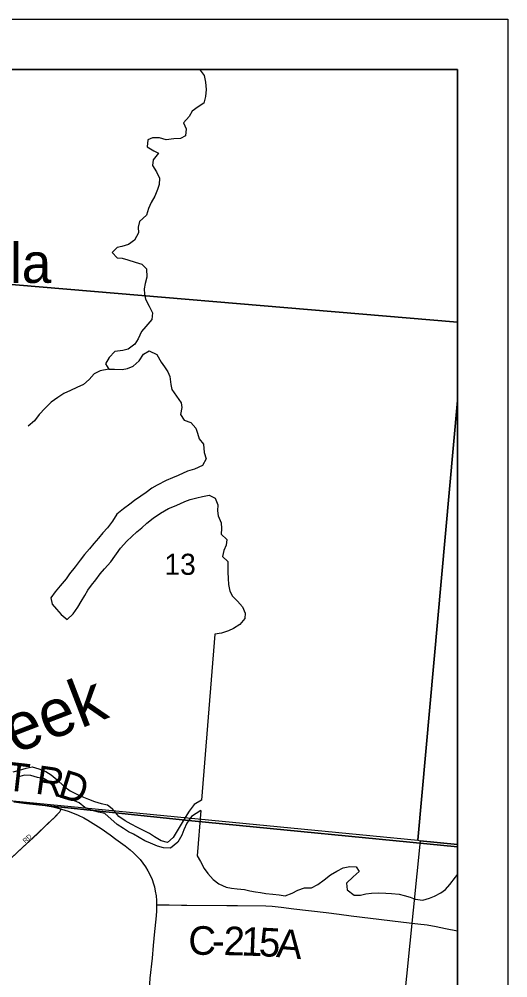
# Model space of a CAD drawing. Extents: x -209 to 4852, y 0 to 905.
# Drawn here: x 177.93 to 197.34, y 302.47 to 340.56 of the extents above; entities that cross this region are included whole.
import ezdxf

# ---------------------------------------------------------------- set-up
doc = ezdxf.new("R2010")
doc.units = 0
for name, color, linetype in [('Default', 7, 'Continuous'), ('GM_P_County_Alignment', 7, 'Continuous'), ('GM_X_Airport_Location_Class_2', 7, 'Continuous'), ('GM_X_Airport_Location_Class_3', 7, 'Continuous'), ('GM_X_Airport_Text_Class_2', 7, 'Continuous'), ('GM_X_Airport_Text_Class_3', 7, 'Continuous'), ('GM_X_County_Road', 7, 'Continuous'), ('GM_X_County_Road_Text', 7, 'Continuous'), ('GM_X_Major_Lake', 7, 'Continuous'), ('GM_X_Minor_Lake_Text', 7, 'Continuous'), ('GM_X_Minor_River', 7, 'Continuous'), ('GM_X_Township_Road_Text', 7, 'Continuous'), ('GM_X_Unincorporated_Location', 7, 'Continuous'), ('GM_X_US_Location', 7, 'Continuous'), ('SH_Data', 7, 'Continuous')]:
    doc.layers.add(name, color=color, linetype=linetype)

msp = doc.modelspace()

# ---------------------------------------------------------------- linework, layer by layer
at = {"layer": 'Default'}
for points in [[(59.342, 338.559), (195.342, 338.559), (195.342, 202.559), (59.342, 202.559)], [(195.342, 202.559), (195.342, 338.559), (59.342, 338.559), (59.342, 202.559)]]:
    msp.add_lwpolyline(points, close=True, dxfattribs=at)
at = {"layer": 'GM_X_Airport_Location_Class_2'}
msp.add_lwpolyline([(176.659, 306.378), (177.055, 306.717), (177.329, 306.965), (177.607, 307.219), (177.88, 307.473), (178.064, 307.641), (178.34, 307.893), (178.656, 308.192), (179.059, 308.583), (179.356, 308.867), (179.377, 308.887), (179.517, 309.031), (179.543, 309.066), (179.572, 309.12), (179.603, 309.175)], dxfattribs=at)
at = {"layer": 'GM_X_Airport_Text_Class_2'}
for points in [[(185.101, 338.559), (185.121, 338.539), (185.285, 338.317), (185.334, 338.058), (185.361, 337.762), (185.334, 337.481), (185.27, 337.224), (185.041, 337.075), (184.804, 336.904), (184.688, 336.693), (184.465, 336.438), (184.56, 336.201), (184.541, 335.921), (184.336, 335.817), (184.07, 335.798), (183.767, 335.764), (183.503, 335.85), (183.23, 335.846), (183.04, 335.765), (183.013, 335.485), (183.276, 335.322), (183.472, 335.229), (183.257, 334.966), (183.231, 334.746), (183.387, 334.494), (183.512, 334.242), (183.494, 333.991), (183.43, 333.787), (183.321, 333.523), (183.181, 333.274), (183.064, 333.033), (182.993, 332.768), (182.709, 332.514), (182.661, 332.295), (182.666, 332.067), (182.518, 331.78), (182.273, 331.601), (182.015, 331.529), (181.825, 331.486), (181.625, 331.283), (181.82, 331.076), (182.024, 331.058), (182.25, 331.002), (182.537, 330.907), (182.801, 330.828), (182.995, 330.636), (183.006, 330.302), (182.934, 330.06), (182.894, 329.848), (182.906, 329.628), (182.956, 329.43), (183.097, 329.162), (183.229, 328.887), (183.203, 328.622), (182.957, 328.352), (182.796, 328.149), (182.663, 327.862), (182.524, 327.652), (182.256, 327.45), (182.051, 327.4)], [(182.051, 327.4), (181.732, 327.352), (181.507, 327.115), (181.364, 326.86), (181.488, 326.652), (181.723, 326.654), (182.026, 326.641)], [(182.026, 326.641), (182.231, 326.676), (182.459, 326.772), (182.704, 326.982), (182.875, 327.245), (183.096, 327.379), (183.397, 327.238), (183.575, 326.932), (183.701, 326.741), (183.842, 326.55), (183.915, 326.359), (183.957, 326.047), (183.992, 325.849), (184.363, 325.313), (184.391, 325.123), (184.335, 324.851), (184.491, 324.621), (184.747, 324.534), (184.948, 324.304), (185.014, 324.106), (185.079, 323.885), (185.258, 323.67), (185.276, 323.343), (185.356, 323.092), (185.217, 322.821), (184.897, 322.68), (184.623, 322.6), (184.242, 322.423), (184.021, 322.335), (183.777, 322.224), (183.419, 322.047), (183.205, 321.92), (182.976, 321.749), (182.762, 321.6), (182.517, 321.428), (182.326, 321.287), (182.074, 321.108), (181.814, 320.891)], [(181.962, 319.545), (182.208, 319.816), (182.408, 320.01), (182.607, 320.19), (182.799, 320.354), (183.005, 320.534), (183.258, 320.728), (183.541, 320.937), (183.869, 321.115), (184.097, 321.211), (184.318, 321.306), (184.508, 321.388), (184.729, 321.476), (184.988, 321.541), (185.216, 321.599), (185.481, 321.648), (185.722, 321.524), (185.824, 321.264), (185.814, 321.029), (185.841, 320.831), (185.951, 320.542), (185.963, 320.321), (185.96, 320.094), (186.185, 319.878), (186.159, 319.658), (186.058, 319.447), (186.002, 319.205), (186.226, 319.005), (186.216, 318.785), (186.221, 318.587), (186.232, 318.337), (186.244, 318.101), (186.294, 317.827), (186.412, 317.636), (186.599, 317.436), (186.808, 317.206), (186.911, 316.954), (186.893, 316.749), (186.7, 316.509), (186.448, 316.353), (186.243, 316.249), (185.969, 316.162), (185.703, 316.119)], [(181.814, 320.891), (181.645, 320.613), (181.44, 320.348), (181.261, 320.147), (181.082, 319.939), (180.894, 319.724), (180.73, 319.515), (180.52, 319.285), (180.348, 319.069), (180.152, 318.801), (179.933, 318.517), (179.792, 318.324), (179.558, 318.048), (179.355, 317.803), (179.19, 317.571), (179.244, 317.312), (179.414, 317.118), (179.598, 316.902), (179.843, 316.706), (180.076, 316.928), (180.257, 317.189), (180.391, 317.421), (180.541, 317.653), (180.66, 317.87), (180.801, 318.064), (180.981, 318.287), (181.153, 318.519), (181.325, 318.719), (181.566, 318.994), (181.962, 319.545)], [(185.703, 316.119), (185.178, 309.521)], [(185.146, 309.114), (185.002, 307.313)], [(185.002, 307.313), (185.136, 307.084), (185.276, 306.809), (185.425, 306.609), (185.641, 306.371), (185.866, 306.209), (186.152, 306.076), (186.363, 306.028), (186.59, 306.002), (186.878, 305.975), (187.097, 305.927), (187.316, 305.886), (187.512, 305.853), (187.731, 305.82), (188.003, 305.786), (188.253, 305.768), (188.502, 305.727), (188.769, 305.83), (188.998, 305.956), (189.271, 306.043), (189.544, 306.04), (189.796, 306.173), (190.048, 306.367), (190.301, 306.554), (190.553, 306.71), (190.804, 306.836), (191.062, 306.886), (191.32, 306.883), (191.431, 306.691), (191.193, 306.474), (190.94, 306.234), (190.966, 305.961), (191.244, 305.752), (191.486, 305.749), (191.706, 305.799), (191.926, 305.834), (192.214, 305.846), (192.494, 305.835), (192.721, 305.824), (193.024, 305.79), (193.22, 305.742), (193.469, 305.67), (193.665, 305.599), (193.96, 305.557), (194.226, 305.63), (194.424, 305.711), (194.675, 305.844), (194.866, 305.971), (195.036, 306.181), (195.259, 306.467), (195.342, 306.568)]]:
    msp.add_lwpolyline(points, dxfattribs=at)
at = {"layer": 'GM_X_County_Road'}
msp.add_lwpolyline([(181.488, 326.652), (181.154, 326.582), (180.911, 326.47), (180.706, 326.244), (180.485, 326.041), (180.219, 325.929), (179.976, 325.81), (179.71, 325.69), (179.467, 325.533), (179.201, 325.337), (178.964, 325.104), (178.728, 324.848), (178.537, 324.599), (178.293, 324.381)], dxfattribs=at)
at = {"layer": 'GM_X_County_Road_Text'}
for points in [[(177.725, 309.458), (177.859, 309.444), (178.225, 309.401), (178.964, 309.31), (179.123, 309.283), (179.272, 309.256), (179.432, 309.222), (179.603, 309.175)], [(179.603, 309.175), (179.616, 309.171), (179.88, 309.085), (180.051, 309.022), (180.281, 308.925), (180.499, 308.821), (180.663, 308.731), (180.874, 308.602), (181.184, 308.397), (181.542, 308.145), (181.77, 307.982), (182.142, 307.707), (182.335, 307.554), (182.475, 307.432), (182.608, 307.303), (182.734, 307.168), (182.85, 307.024), (182.955, 306.875), (183.048, 306.716), (183.135, 306.55), (183.209, 306.381), (183.27, 306.206), (183.301, 306.088), (183.339, 305.907), (183.368, 305.725), (183.384, 305.54), (183.388, 305.368)], [(183.388, 305.368), (183.389, 305.355), (183.382, 305.109), (183.356, 304.798), (183.311, 304.307), (183.258, 303.749), (183.21, 303.255), (183.126, 302.449), (183.103, 302.226), (183.038, 301.587), (183.005, 301.217), (182.926, 300.419), (182.868, 299.765), (182.794, 298.991), (182.686, 297.825), (182.629, 297.202), (182.545, 296.397), (182.542, 296.354)], [(183.388, 305.368), (183.486, 305.368), (183.884, 305.366), (184.377, 305.359), (184.587, 305.357)], [(184.587, 305.357), (186.177, 305.34), (186.599, 305.337), (187.726, 305.327), (187.977, 305.314), (187.986, 305.313)], [(187.986, 305.313), (188.345, 305.272), (188.847, 305.212), (190.122, 305.06), (190.647, 304.998), (191.115, 304.935), (192.657, 304.745), (193.192, 304.684), (193.767, 304.613), (194.133, 304.569), (194.5, 304.502), (194.862, 304.433), (195.342, 304.334)]]:
    msp.add_lwpolyline(points, dxfattribs=at)
at = {"layer": 'GM_X_Major_Lake'}
for points in [[(177.688, 310.653), (177.948, 310.723), (178.208, 310.793), (178.452, 310.848), (178.716, 310.774), (178.986, 310.661), (179.203, 310.527), (179.434, 310.331), (179.701, 310.082), (179.963, 309.901), (180.27, 309.734), (180.488, 309.645), (180.683, 309.565), (180.924, 309.476), (181.188, 309.401), (181.437, 309.342), (181.631, 309.193)], [(181.824, 308.554), (181.338, 309.002), (181.081, 309.054), (180.794, 309.129), (180.546, 309.234), (180.316, 309.421), (180.03, 309.535), (179.765, 309.579), (179.511, 309.722), (179.365, 309.991), (179.151, 310.247), (178.919, 310.374), (178.655, 310.433), (178.398, 310.507), (178.141, 310.521), (177.865, 310.436)], [(185.178, 309.521), (184.878, 309.35), (184.678, 309.087), (184.531, 308.838), (184.368, 308.567), (184.205, 308.303), (184.05, 308.04), (183.828, 307.845), (183.572, 307.909), (183.309, 308.072), (183.106, 308.196), (182.85, 308.336), (182.632, 308.437), (182.384, 308.57), (182.144, 308.71), (181.888, 308.872), (181.631, 309.193)], [(185.146, 309.114), (184.773, 308.873), (184.588, 308.617), (184.471, 308.353), (184.393, 308.141), (184.23, 307.855), (183.939, 307.623), (183.666, 307.627), (183.425, 307.698), (183.146, 307.823), (182.928, 307.917), (182.703, 308.049), (182.47, 308.181), (182.274, 308.275), (182.071, 308.399), (181.824, 308.554)]]:
    msp.add_lwpolyline(points, dxfattribs=at)
at = {"layer": 'GM_X_Minor_Lake_Text'}
for points in [[(177.725, 309.458), (178.225, 309.401), (184.794, 308.709), (195.342, 307.677), (195.342, 338.559), (102.839, 338.559)], [(61.776, 202.559), (195.342, 202.559), (195.342, 307.677), (184.794, 308.709), (178.225, 309.401), (177.725, 309.458)]]:
    msp.add_lwpolyline(points, dxfattribs=at)
at = {"layer": 'GM_X_Minor_River'}
for points in [[(195.342, 328.517), (195.342, 338.559), (175.676, 338.559), (174.954, 330.248)], [(195.342, 325.41), (195.342, 328.517), (174.954, 330.248), (173.108, 309.953), (173.577, 309.901), (193.768, 307.931)], [(195.342, 307.769), (195.342, 325.41), (193.768, 307.931), (193.859, 307.914)], [(173.577, 309.901), (193.768, 307.931), (193.859, 307.914), (191.805, 287.574), (171.86, 289.687)], [(195.342, 287.212), (195.342, 307.769), (193.859, 307.914), (191.805, 287.574)]]:
    msp.add_lwpolyline(points, close=True, dxfattribs=at)
at = {"layer": 'GM_X_US_Location'}
msp.add_lwpolyline([(177.607, 307.218), (179.356, 308.867), (179.517, 309.031), (179.543, 309.066), (179.603, 309.175), (179.432, 309.222), (179.272, 309.256), (178.964, 309.309), (177.725, 309.458)], dxfattribs=at)
at = {"layer": 'SH_Data'}
for p, q in [((57.342, 340.559), (197.342, 340.559)), ((197.342, 340.559), (197.342, 200.559))]:
    msp.add_line(p, q, dxfattribs=at)

# ---------------------------------------------------------------- texts
at = {"layer": 'GM_P_County_Alignment'}
for s, rotation, p in [('T', 353.4975, (177.358, 309.93)), ('R', 351.7832, (178.542, 309.794)), ('D', 342.7931, (179.419, 309.671)), ('C', 359.3599, (184.647, 303.389)), ('2', 358.9071, (186.044, 303.372)), ('1', 357.9284, (186.739, 303.359)), ('5', 356.996, (187.434, 303.334)), ('A', 354.8788, (188.122, 303.298)), ('-', 359.2506, (185.579, 303.378))]:
    msp.add_text(s, height=1.136, rotation=rotation, dxfattribs=at).set_placement(p)
at = {"layer": 'GM_X_Airport_Location_Class_3'}
msp.add_text('RD', height=0.1894, rotation=42.8801, dxfattribs=at).set_placement((178.177, 307.806))
at = {"layer": 'GM_X_Airport_Text_Class_3'}
msp.add_text('Creek', height=1.8941, rotation=21.0113, dxfattribs=at).set_placement((175.249, 310.403))
at = {"layer": 'GM_X_Township_Road_Text'}
msp.add_text('13', height=0.8371, rotation=0, dxfattribs=at).set_placement((183.702, 318.481))
at = {"layer": 'GM_X_Unincorporated_Location'}
msp.add_text('Villa', height=1.5795, rotation=0, dxfattribs=at).set_placement((175.218, 330.079))

doc.saveas('drawing.dxf')
